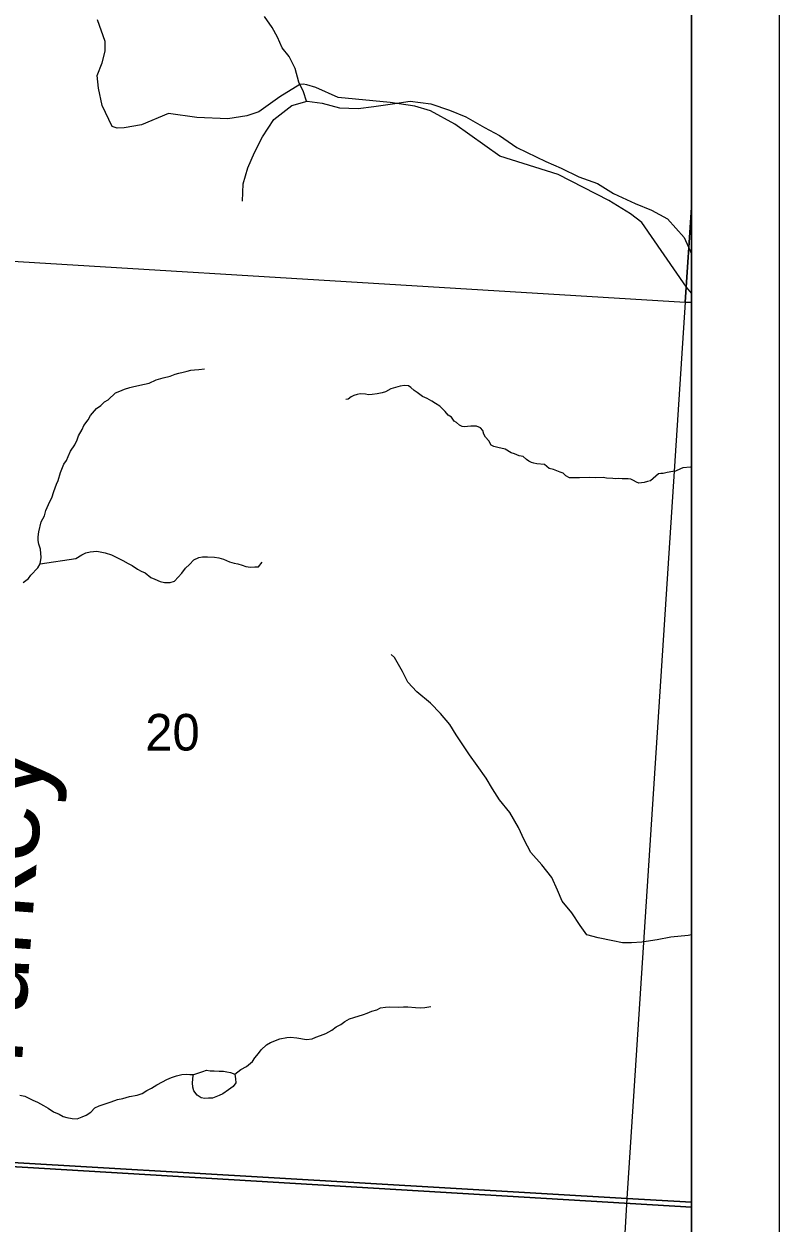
# Model space of a CAD drawing. Extents: x 0 to 34, y 0 to 22.
# Drawn here: x 8.137 to 9, y 16.183 to 17.554 of the extents above; entities that cross this region are included whole.
import ezdxf

# ---------------------------------------------------------------- set-up
doc = ezdxf.new("R2010")
doc.units = 0
for name, color, linetype in [('GM_X_Corporation', 7, 'Continuous'), ('GM_X_County_Road', 7, 'Continuous'), ('GM_X_Minor_River', 7, 'Continuous'), ('GM_X_Minor_River_Text', 7, 'Continuous'), ('GM_X_Section_Text', 7, 'Continuous'), ('SH_Data', 7, 'Continuous')]:
    doc.layers.add(name, color=color, linetype=linetype)

msp = doc.modelspace()

# ---------------------------------------------------------------- linework, layer by layer
at = {"layer": 'GM_X_Corporation'}
for points in [[(3.3441, 14.1), (8.9, 14.1), (8.9, 20.9), (2.1, 20.9), (2.1, 16.1353), (2.1457, 16.065), (2.3447, 15.6926), (2.4297, 15.5215), (2.465, 15.4504), (2.4884, 15.4033), (2.5769, 15.2135), (2.7849, 14.8403), (2.8931, 14.6544), (3.0297, 14.4867), (3.1386, 14.3654), (3.228, 14.2415)], [(8.9, 16.2015), (8.9, 20.2763), (8.59, 20.3005), (8.3805, 20.3169), (8.0028, 20.34), (6.9032, 20.4198), (6.8961, 20.3303), (6.835, 19.4037), (6.824, 19.3005), (6.7876, 18.7583), (6.7629, 18.3924), (6.7536, 18.2991), (6.7043, 17.4985), (6.6962, 17.3669), (6.6852, 17.2401), (6.6249, 16.3344), (7.5782, 16.28), (7.7162, 16.2721), (7.873, 16.2628)], [(8.9, 17.3437), (8.9, 18.2556), (7.864, 18.3242), (7.7921, 17.3025), (8.8926, 17.2358)], [(8.9, 17.2354), (8.9, 17.3437), (8.8926, 17.2358)], [(7.7921, 17.3025), (8.8926, 17.2358), (8.826, 16.2114), (7.7202, 16.2762)], [(8.9, 16.207), (8.9, 17.2354), (8.8926, 17.2358), (8.826, 16.2114)], [(5.4627, 14.1), (8.9, 14.1), (8.9, 16.2015), (7.873, 16.2628), (7.7162, 16.2721), (7.5782, 16.28), (6.6249, 16.3344), (6.6163, 16.2457), (5.9321, 16.289), (5.8351, 16.2952), (5.6497, 16.3069), (5.6022, 16.3258), (5.5809, 15.9822), (5.4893, 14.5091), (5.4833, 14.4122), (5.4763, 14.3006)], [(7.7202, 16.2762), (8.826, 16.2114), (8.7674, 15.1938), (7.66, 15.265)], [(8.9, 15.1859), (8.9, 16.207), (8.826, 16.2114), (8.7674, 15.1938)]]:
    msp.add_lwpolyline(points, close=True, dxfattribs=at)
at = {"layer": 'GM_X_County_Road'}
msp.add_lwpolyline([(8.9, 17.2458), (8.8943, 17.2527), (8.8431, 17.3268), (8.8302, 17.3365), (8.8053, 17.3519), (8.7476, 17.3814), (8.6809, 17.4025), (8.6293, 17.4389), (8.6015, 17.4544), (8.5835, 17.4598), (8.5554, 17.4637), (8.496, 17.4697), (8.4705, 17.4809), (8.4602, 17.4841), (8.4559, 17.4847), (8.4522, 17.4845), (8.4295, 17.4702), (8.4053, 17.4533), (8.3915, 17.4487), (8.3697, 17.445), (8.3343, 17.4466), (8.302, 17.4512), (8.2713, 17.4384), (8.2515, 17.4349), (8.2434, 17.4343), (8.2375, 17.4362), (8.2263, 17.4604), (8.2221, 17.48), (8.2206, 17.4946), (8.2262, 17.5091), (8.2296, 17.5225), (8.2298, 17.5335), (8.2208, 17.5581)], dxfattribs=at)
at = {"layer": 'GM_X_Minor_River'}
for points in [[(8.46, 17.4654), (8.4563, 17.476), (8.451, 17.487), (8.4469, 17.5026), (8.4401, 17.5162), (8.4321, 17.5264), (8.4268, 17.5386), (8.4204, 17.5496), (8.4117, 17.5621)], [(8.3867, 17.3511), (8.3875, 17.3708), (8.3928, 17.389), (8.4005, 17.4065), (8.4096, 17.4246), (8.4225, 17.4443), (8.443, 17.4602), (8.4604, 17.4655), (8.4778, 17.4632), (8.4975, 17.4578), (8.5187, 17.457), (8.5369, 17.4592), (8.5581, 17.4622), (8.5785, 17.4652), (8.602, 17.4621), (8.6232, 17.4552), (8.6421, 17.4475), (8.6632, 17.4353), (8.6806, 17.4262), (8.7002, 17.4125), (8.7335, 17.3964), (8.7509, 17.3888), (8.7713, 17.3789), (8.7925, 17.3712), (8.8106, 17.3598), (8.8355, 17.3483), (8.8544, 17.3407), (8.8726, 17.3308), (8.8914, 17.3095), (8.9, 17.2907)], [(8.136, 16.9152), (8.1421, 16.9197), (8.1448, 16.9238), (8.1526, 16.932), (8.1553, 16.9365), (8.1566, 16.9437), (8.1556, 16.9533), (8.1538, 16.959), (8.1531, 16.9632), (8.1532, 16.9674), (8.1537, 16.973), (8.1565, 16.9844), (8.1604, 16.9916), (8.162, 16.9976), (8.1664, 17.0078), (8.1687, 17.0119), (8.1708, 17.0191), (8.1739, 17.0278), (8.1759, 17.032), (8.1787, 17.041), (8.1823, 17.0505), (8.1854, 17.0546), (8.1874, 17.0591), (8.1901, 17.0655), (8.1948, 17.0727), (8.1976, 17.0783), (8.1991, 17.0829), (8.2034, 17.09), (8.2054, 17.0945), (8.2101, 17.1013), (8.2128, 17.1062), (8.2198, 17.1141), (8.2248, 17.1174), (8.229, 17.1219), (8.2332, 17.1241), (8.2413, 17.1319), (8.2463, 17.1341), (8.2516, 17.1363), (8.2577, 17.1381), (8.2626, 17.1392), (8.2748, 17.142), (8.2801, 17.1431), (8.2878, 17.1467), (8.2961, 17.1493), (8.3038, 17.151), (8.3095, 17.1532), (8.314, 17.1543), (8.319, 17.1557), (8.3235, 17.1568), (8.3277, 17.1579), (8.3319, 17.1582), (8.3368, 17.1588), (8.3433, 17.1595)], [(8.9, 17.0473), (8.8989, 17.0472), (8.8901, 17.0462), (8.8875, 17.0451), (8.8818, 17.0425), (8.8787, 17.0422), (8.8723, 17.0408), (8.8677, 17.0397), (8.865, 17.0398), (8.8624, 17.0394), (8.8531, 17.0316), (8.8497, 17.0305), (8.8459, 17.0294), (8.8398, 17.0288), (8.8372, 17.03), (8.8338, 17.0319), (8.8305, 17.0335), (8.8274, 17.0339), (8.824, 17.0336), (8.8206, 17.0337), (8.8168, 17.0341), (8.813, 17.0338), (8.81, 17.0342), (8.8028, 17.0343), (8.799, 17.0352), (8.7907, 17.0349), (8.7831, 17.0351), (8.7718, 17.0349), (8.7634, 17.035), (8.7604, 17.0347), (8.7563, 17.037), (8.7533, 17.0401), (8.7499, 17.0413), (8.742, 17.0445), (8.7371, 17.0457), (8.7319, 17.05), (8.7232, 17.0509), (8.7198, 17.0517), (8.7172, 17.0525), (8.7138, 17.0541), (8.7112, 17.0557), (8.7074, 17.0591), (8.7029, 17.06), (8.6976, 17.0623), (8.6939, 17.0635), (8.6871, 17.0678), (8.6784, 17.0695), (8.6739, 17.0707), (8.6709, 17.0723), (8.6684, 17.0773), (8.6646, 17.0815), (8.6624, 17.0846), (8.6614, 17.0888), (8.6588, 17.0919), (8.6542, 17.0938), (8.6478, 17.094), (8.6402, 17.0933), (8.6376, 17.0934), (8.6346, 17.0949), (8.6312, 17.098), (8.6286, 17.0996), (8.6256, 17.1042), (8.6219, 17.1066), (8.6182, 17.1108), (8.6122, 17.1166), (8.6074, 17.1197), (8.6032, 17.1224), (8.5976, 17.1256), (8.5924, 17.1279), (8.5864, 17.1322), (8.583, 17.1346), (8.5789, 17.1381), (8.5763, 17.14), (8.5717, 17.1405), (8.5668, 17.1398), (8.5561, 17.1365), (8.55, 17.1332), (8.5462, 17.1321), (8.5405, 17.1307), (8.5348, 17.1301), (8.5306, 17.1297), (8.5272, 17.1306), (8.5212, 17.1307), (8.5178, 17.13), (8.514, 17.1289), (8.5109, 17.1274), (8.5074, 17.1248), (8.5048, 17.1245)], [(8.1553, 16.9365), (8.1963, 16.9427), (8.2028, 16.9468), (8.2074, 16.949), (8.2124, 16.9504), (8.2203, 16.951), (8.2298, 16.949), (8.2369, 16.947), (8.2497, 16.9403), (8.2561, 16.9371), (8.2606, 16.9348), (8.2665, 16.9305), (8.2707, 16.9281), (8.2752, 16.9262), (8.2819, 16.9211), (8.2864, 16.9191), (8.2924, 16.9164), (8.2973, 16.9152), (8.3038, 16.9154), (8.3091, 16.9169), (8.313, 16.9214), (8.3172, 16.9258), (8.3215, 16.9315), (8.3261, 16.936), (8.3311, 16.9412), (8.3369, 16.9438), (8.341, 16.9444), (8.3467, 16.9447), (8.3547, 16.9442), (8.3596, 16.9434), (8.3648, 16.9418), (8.3716, 16.939), (8.3773, 16.9374), (8.3814, 16.9365), (8.3863, 16.9349), (8.3905, 16.9337), (8.3958, 16.9329), (8.4007, 16.9332), (8.4048, 16.9331), (8.4091, 16.9384)], [(8.9, 16.5125), (8.8963, 16.5118), (8.8762, 16.5099), (8.8607, 16.5069), (8.8433, 16.5042), (8.8312, 16.5035), (8.8209, 16.5035), (8.81, 16.5057), (8.7933, 16.5091), (8.7801, 16.5126), (8.7725, 16.5232), (8.763, 16.5376), (8.7521, 16.5512), (8.7468, 16.5637), (8.7404, 16.5781), (8.729, 16.5925), (8.7161, 16.6065), (8.7086, 16.6213), (8.7021, 16.6353), (8.6923, 16.6524), (8.6806, 16.6668), (8.6723, 16.6793), (8.6651, 16.6918), (8.6549, 16.7062), (8.6461, 16.7183), (8.631, 16.741), (8.6238, 16.7528), (8.6129, 16.7657), (8.6015, 16.7774), (8.586, 16.7903), (8.5758, 16.8013), (8.5697, 16.8134), (8.5606, 16.8297), (8.5565, 16.8331)], [(8.378, 16.3534), (8.3849, 16.3586), (8.3914, 16.3623), (8.3979, 16.3679), (8.4007, 16.372), (8.4049, 16.3769), (8.408, 16.381), (8.4142, 16.387), (8.4188, 16.3896), (8.4295, 16.3936), (8.4374, 16.3953), (8.4416, 16.3957), (8.4488, 16.3948), (8.4597, 16.3931), (8.4662, 16.3937), (8.4704, 16.3956), (8.4757, 16.3974), (8.4818, 16.3999), (8.4887, 16.4036), (8.4937, 16.4073), (8.4991, 16.4103), (8.5037, 16.4136), (8.509, 16.4166), (8.514, 16.418), (8.525, 16.4216), (8.5292, 16.4231), (8.5346, 16.4252), (8.5403, 16.4267), (8.5445, 16.4293), (8.5502, 16.4299), (8.5543, 16.4302), (8.5649, 16.4301), (8.5706, 16.4303), (8.5755, 16.4303), (8.5843, 16.4297), (8.5899, 16.4293), (8.5949, 16.4296), (8.6021, 16.4306)], [(8.1321, 16.3294), (8.1378, 16.3282), (8.1468, 16.3235), (8.1524, 16.3215), (8.1592, 16.3176), (8.1644, 16.3145), (8.1704, 16.3105), (8.1772, 16.3078), (8.1817, 16.305), (8.1858, 16.3038), (8.1919, 16.3026), (8.1976, 16.3025), (8.2033, 16.3047), (8.2079, 16.3065), (8.2132, 16.3098), (8.2178, 16.3147), (8.2228, 16.3173), (8.2365, 16.3216), (8.2438, 16.3245), (8.2499, 16.3256), (8.2575, 16.3277), (8.2662, 16.3295), (8.2719, 16.3313), (8.2773, 16.3346), (8.2826, 16.3375), (8.2888, 16.3412), (8.2953, 16.3445), (8.3002, 16.3471), (8.3056, 16.3497), (8.3113, 16.3515), (8.3174, 16.3529), (8.3223, 16.3532), (8.3265, 16.3528), (8.331, 16.3531), (8.3413, 16.3563), (8.3455, 16.3578), (8.3497, 16.3573), (8.3542, 16.3572), (8.3599, 16.3568), (8.3648, 16.3567), (8.3689, 16.3562), (8.3731, 16.3554), (8.378, 16.3534), (8.3787, 16.3481), (8.379, 16.3435), (8.3759, 16.3394), (8.3705, 16.3353), (8.364, 16.3309), (8.3598, 16.329), (8.3525, 16.3261), (8.3476, 16.3258), (8.3434, 16.3255), (8.3393, 16.3263), (8.3348, 16.3294), (8.3311, 16.3344), (8.33, 16.3386), (8.3293, 16.3436), (8.3302, 16.3519), (8.3306, 16.353)]]:
    msp.add_lwpolyline(points, dxfattribs=at)
at = {"layer": 'SH_Data'}
for p, q in [((9, 21), (9, 14)), ((8.9, 20.9), (8.9, 14.1))]:
    msp.add_line(p, q, dxfattribs=at)

# ---------------------------------------------------------------- texts
at = {"layer": 'GM_X_Minor_River_Text'}
msp.add_text('Turkey', height=0.09471, rotation=85.7613, dxfattribs=at).set_placement((8.1325, 16.3401))
at = {"layer": 'GM_X_Section_Text'}
msp.add_text('20', height=0.04186, rotation=0, dxfattribs=at).set_placement((8.2755, 16.7232))

doc.saveas('drawing.dxf')
